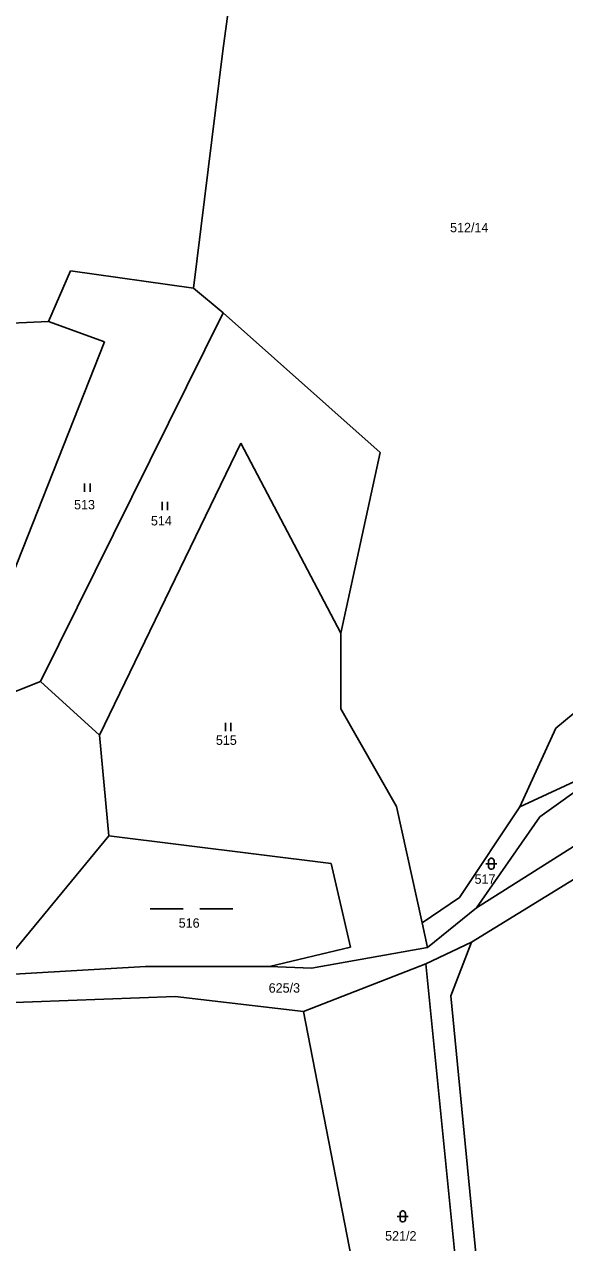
# Model space of a CAD drawing. Extents: x -794421 to -792735, y -1117671 to -1115559.
# Drawn here: x -793818.1 to -793720, y -1117244.8 to -1117024 of the extents above; entities that cross this region are included whole.
import ezdxf

# ---------------------------------------------------------------- set-up
doc = ezdxf.new("R2010")
doc.units = 0
for name, color, linetype in [('Vrstva 1', 7, 'Continuous'), ('Vrstva 14', 7, 'Continuous'), ('Vrstva 23', 7, 'Continuous')]:
    doc.layers.add(name, color=color, linetype=linetype)

msp = doc.modelspace()

# ---------------------------------------------------------------- linework, layer by layer
at = {"layer": 'Vrstva 1'}
for p, q in [((-793773.41, -1116965.63), (-793782.04, -1117028.77)), ((-793782.04, -1117028.77), (-793787.4, -1117071.74)), ((-793813.68, -1117077.82), (-793809.72, -1117068.61)), ((-793809.72, -1117068.61), (-793787.4, -1117071.74)), ((-793787.4, -1117071.74), (-793782.02, -1117076.24)), ((-793827.45, -1117078.43), (-793813.68, -1117077.82)), ((-793815.11, -1117143.08), (-793782.02, -1117076.24)), ((-793803.5, -1117081.51), (-793813.68, -1117077.82)), ((-793782.02, -1117076.24), (-793753.52, -1117101.58)), ((-793830.24, -1117149), (-793803.5, -1117081.51)), ((-793778.81, -1117099.86), (-793804.44, -1117152.77)), ((-793760.62, -1117134.3), (-793778.81, -1117099.86)), ((-793753.52, -1117101.58), (-793760.62, -1117134.3)), ((-793760.62, -1117134.3), (-793760.62, -1117148.02)), ((-793708.04, -1117140.29), (-793721.63, -1117151.49)), ((-793830.24, -1117149), (-793815.11, -1117143.08)), ((-793815.11, -1117143.08), (-793804.44, -1117152.77)), ((-793760.62, -1117148.02), (-793750.55, -1117165.71)), ((-793804.44, -1117152.77), (-793802.76, -1117171.03)), ((-793721.63, -1117151.49), (-793728.18, -1117165.77)), ((-793710.4, -1117157.5), (-793728.18, -1117165.77)), ((-793710.4, -1117157.5), (-793724.56, -1117167.56)), ((-793750.55, -1117165.71), (-793745.92, -1117186.82)), ((-793728.18, -1117165.77), (-793739.11, -1117182.21)), ((-793724.56, -1117167.56), (-793736.01, -1117184.09)), ((-793823.59, -1117196.32), (-793802.76, -1117171.03)), ((-793802.76, -1117171.03), (-793762.39, -1117176.04)), ((-793736.01, -1117184.09), (-793714, -1117170.15)), ((-793736.92, -1117190.31), (-793710.4, -1117173.99)), ((-793762.39, -1117176.04), (-793758.88, -1117191.19)), ((-793739.11, -1117182.21), (-793745.92, -1117186.82)), ((-793744.95, -1117191.25), (-793736.01, -1117184.09)), ((-793745.92, -1117186.82), (-793744.95, -1117191.25)), ((-793736.92, -1117190.31), (-793745.22, -1117194.22)), ((-793740.7, -1117200.01), (-793736.92, -1117190.31)), ((-793758.88, -1117191.19), (-793773.58, -1117194.71)), ((-793744.95, -1117191.25), (-793765.94, -1117195)), ((-793796.11, -1117194.74), (-793823.59, -1117196.32)), ((-793773.58, -1117194.71), (-793796.11, -1117194.74)), ((-793765.94, -1117195), (-793773.58, -1117194.71)), ((-793767.43, -1117202.86), (-793745.22, -1117194.22)), ((-793745.22, -1117194.22), (-793734.99, -1117296.17)), ((-793830.98, -1117201.68), (-793790.72, -1117200.13)), ((-793790.72, -1117200.13), (-793767.43, -1117202.86)), ((-793731.46, -1117294.94), (-793740.7, -1117200.01)), ((-793758.11, -1117250.74), (-793767.43, -1117202.86))]:
    msp.add_line(p, q, dxfattribs=at)
at = {"layer": 'Vrstva 23'}
for p, q in [((-793807.14, -1117108.67), (-793807.14, -1117107.17)), ((-793806.14, -1117107.17), (-793806.14, -1117108.67)), ((-793793.09, -1117111.99), (-793793.09, -1117110.49)), ((-793792.09, -1117110.49), (-793792.09, -1117111.99)), ((-793781.58, -1117152.04), (-793781.58, -1117150.54)), ((-793780.58, -1117150.54), (-793780.58, -1117152.04)), ((-793733.84, -1117175.5), (-793733.74, -1117175.3)), ((-793733.84, -1117176.7), (-793733.84, -1117175.5)), ((-793733.74, -1117175.3), (-793733.64, -1117175.2)), ((-793733.64, -1117175.2), (-793733.44, -1117175.1)), ((-793733.44, -1117175.1), (-793733.24, -1117175.1)), ((-793733.24, -1117175.1), (-793733.04, -1117175.2)), ((-793733.04, -1117175.2), (-793732.94, -1117175.3)), ((-793732.94, -1117175.3), (-793732.84, -1117175.5)), ((-793732.84, -1117175.5), (-793732.84, -1117176.7)), ((-793734.34, -1117176.1), (-793732.34, -1117176.1)), ((-793733.74, -1117176.9), (-793733.84, -1117176.7)), ((-793733.64, -1117177), (-793733.74, -1117176.9)), ((-793733.44, -1117177.1), (-793733.64, -1117177)), ((-793733.24, -1117177.1), (-793733.44, -1117177.1)), ((-793733.04, -1117177), (-793733.24, -1117177.1)), ((-793732.94, -1117176.9), (-793733.04, -1117177)), ((-793732.84, -1117176.7), (-793732.94, -1117176.9)), ((-793795.23, -1117184.28), (-793789.23, -1117184.28)), ((-793786.23, -1117184.28), (-793780.23, -1117184.28)), ((-793749.91, -1117239.41), (-793749.81, -1117239.21)), ((-793749.91, -1117240.61), (-793749.91, -1117239.41)), ((-793749.81, -1117239.21), (-793749.71, -1117239.11)), ((-793749.71, -1117239.11), (-793749.51, -1117239.01)), ((-793749.51, -1117239.01), (-793749.31, -1117239.01)), ((-793749.31, -1117239.01), (-793749.11, -1117239.11)), ((-793749.11, -1117239.11), (-793749.01, -1117239.21)), ((-793749.01, -1117239.21), (-793748.91, -1117239.41)), ((-793748.91, -1117239.41), (-793748.91, -1117240.61)), ((-793750.41, -1117240.01), (-793748.41, -1117240.01)), ((-793749.81, -1117240.81), (-793749.91, -1117240.61)), ((-793749.71, -1117240.91), (-793749.81, -1117240.81)), ((-793749.51, -1117241.01), (-793749.71, -1117240.91)), ((-793749.31, -1117241.01), (-793749.51, -1117241.01)), ((-793749.11, -1117240.91), (-793749.31, -1117241.01)), ((-793749.01, -1117240.81), (-793749.11, -1117240.91)), ((-793748.91, -1117240.61), (-793749.01, -1117240.81))]:
    msp.add_line(p, q, dxfattribs=at)

# ---------------------------------------------------------------- texts
at = {"layer": 'Vrstva 14'}
for s, p in [('512/14', (-793740.828, -1117061.63)), ('513', (-793809.046, -1117111.86)), ('514', (-793795.102, -1117114.77)), ('515', (-793783.313, -1117154.54)), ('517', (-793736.383, -1117179.72)), ('516', (-793790.066, -1117187.68)), ('625/3', (-793773.736, -1117199.45)), ('521/2', (-793752.609, -1117244.38))]:
    msp.add_text(s, height=1.7, dxfattribs=at).set_placement(p)

doc.saveas('drawing.dxf')
